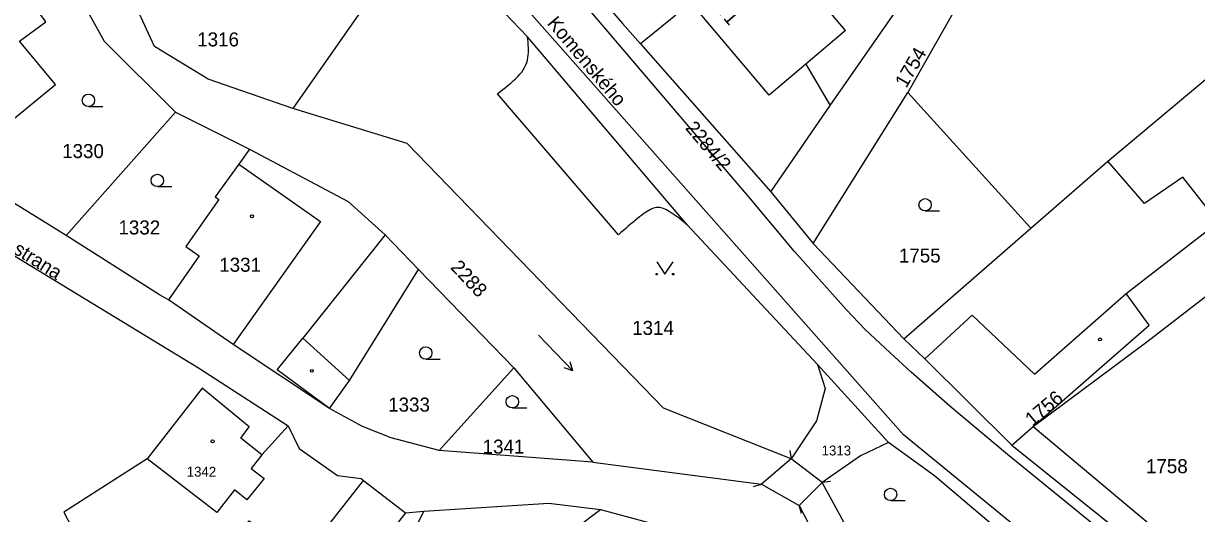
# Model space of a CAD drawing. Extents: x -504988 to -494607, y -1123820 to -1114018.
# Drawn here: x -498003.8 to -497861.7, y -1119159 to -1119099.6 of the extents above; entities that cross this region are included whole.
import ezdxf

# ---------------------------------------------------------------- set-up
doc = ezdxf.new("R2010")
doc.units = 0
for name, color, linetype in [('Hranice parcel', 7, 'Continuous'), ('Parcelní čísla', 7, 'Continuous'), ('Pop  PČ popisy', 7, 'Continuous'), ('Vnitřní kresba', 7, 'Continuous'), ('Značky budov', 7, 'Continuous'), ('Značky kultur', 7, 'Continuous')]:
    doc.layers.add(name, color=color, linetype=linetype)

msp = doc.modelspace()

# ---------------------------------------------------------------- linework, layer by layer
at = {"layer": 'Hranice parcel'}
for p, q in [((-497887.77, -1119092.18), (-497896.72, -1119107.97)), ((-497961.64, -1119096.18), (-497971.21, -1119109.91)), ((-497908.17, -1119126.25), (-497896.72, -1119107.97)), ((-497896.72, -1119107.97), (-497881.83, -1119124.42)), ((-497998.68, -1119125.28), (-497985.41, -1119110.35)), ((-497985.41, -1119110.35), (-497976.46, -1119114.83)), ((-497998.68, -1119125.28), (-498012.13, -1119116.99)), ((-497881.83, -1119124.42), (-497872.49, -1119116.3)), ((-497913.33, -1119120.02), (-497908.17, -1119126.25)), ((-497897.22, -1119137.82), (-497881.83, -1119124.42)), ((-497908.17, -1119126.25), (-497897.22, -1119137.82)), ((-497955.98, -1119129.4), (-497944.43, -1119141.34)), ((-497899.04, -1119150.4), (-497907.66, -1119140.94)), ((-497953.5, -1119151.34), (-497944.43, -1119141.34)), ((-497944.43, -1119141.34), (-497934.86, -1119152.78)), ((-497884.11, -1119150.7), (-497881.53, -1119148.44)), ((-497884.11, -1119150.7), (-497809.18, -1119210.79)), ((-497934.86, -1119152.78), (-497953.5, -1119151.34)), ((-497907.08, -1119155.23), (-497910.85, -1119152.35)), ((-497934.86, -1119152.78), (-497914.46, -1119155.42)), ((-497962.63, -1119154.98), (-497957.58, -1119158.92)), ((-497914.46, -1119155.42), (-497909.86, -1119158.02)), ((-497893.36, -1119180.26), (-497907.08, -1119155.23)), ((-497955.35, -1119158.69), (-497961.68, -1119170.97)), ((-497957.58, -1119158.92), (-497955.35, -1119158.69)), ((-497933.93, -1119158.49), (-497922.1, -1119161.69))]:
    msp.add_line(p, q, dxfattribs=at)
for points in [[(-497910.46, -1119127.22), (-497915.79, -1119120.84), (-497965.51, -1119062.43), (-497969.8, -1119056.29)], [(-497971.21, -1119109.91), (-497981.48, -1119106.35), (-497987.95, -1119102.39), (-497996.54, -1119083.76)], [(-498003.97, -1119085.2), (-498000.56, -1119092.53), (-497998.87, -1119093.04), (-497994.08, -1119101.73), (-497985.41, -1119110.35)], [(-497942.7, -1119086.56), (-497936.66, -1119093.43), (-497933.96, -1119096.51), (-497931.26, -1119099.59), (-497929.09, -1119102.07), (-497913.33, -1119120.02)], [(-497907.66, -1119140.94), (-497923.43, -1119123.99), (-497942.78, -1119101.23), (-497953.93, -1119089.55)], [(-497872.49, -1119116.3), (-497843.78, -1119092.19), (-497840.07, -1119088.75)], [(-498012.13, -1119116.99), (-497999.97, -1119107), (-498004.3, -1119101.73), (-498001.13, -1119099.4), (-498002.9, -1119096.92), (-498003.95, -1119097.55), (-498005.62, -1119095.27), (-498011.54, -1119099.6), (-498020.88, -1119106.56)], [(-497913.33, -1119120.02), (-497906.12, -1119109.53), (-497896.94, -1119096.33)], [(-497910.85, -1119152.35), (-497926.33, -1119146.21), (-497957.34, -1119114.14), (-497971.21, -1119109.91)], [(-497976.46, -1119114.83), (-497977.76, -1119116.63), (-497980.6, -1119120.62), (-497980.18, -1119120.93), (-497984.18, -1119126.62), (-497982.56, -1119127.74), (-497986.27, -1119133.1)], [(-497976.46, -1119114.83), (-497964.52, -1119121.18), (-497960.01, -1119125.23), (-497955.98, -1119129.4)], [(-497881.53, -1119148.44), (-497867.5, -1119136.16), (-497870.27, -1119132.33), (-497859.11, -1119123.69), (-497863.39, -1119118.22), (-497868.05, -1119121.43), (-497872.49, -1119116.3)], [(-497881.53, -1119148.44), (-497867.76, -1119138.19), (-497847.62, -1119122.61)], [(-498010.34, -1119124.5), (-497982.64, -1119141.32), (-497971.78, -1119148.38)], [(-497986.27, -1119133.1), (-497987.35, -1119132.48), (-497998.68, -1119125.28)], [(-497901.88, -1119136.7), (-497904.2, -1119134.26), (-497910.46, -1119127.22)], [(-497966.75, -1119146.25), (-497964.36, -1119142.85), (-497955.98, -1119129.4)], [(-497966.75, -1119146.25), (-497978.45, -1119138.5), (-497986.27, -1119133.1)], [(-497896.33, -1119141.86), (-497898.9, -1119139.46), (-497901.88, -1119136.7)], [(-497897.22, -1119137.82), (-497894.64, -1119140.25), (-497884.11, -1119150.7)], [(-497907.66, -1119140.94), (-497906.71, -1119143.85), (-497907.76, -1119147.75), (-497910.85, -1119152.35)], [(-497884.63, -1119151.84), (-497891.61, -1119145.97), (-497896.33, -1119141.86)], [(-497971.78, -1119148.38), (-497974.95, -1119151.88), (-497977.52, -1119149.84), (-497976.48, -1119148.47), (-497982.2, -1119143.81), (-497988.87, -1119152.35), (-497998.96, -1119158.81), (-497996.1, -1119164.22)], [(-497953.5, -1119151.34), (-497959.31, -1119149.81), (-497962.78, -1119148.46), (-497966.75, -1119146.25)], [(-497971.78, -1119148.38), (-497970.45, -1119151.11), (-497965.81, -1119154.39), (-497962.94, -1119154.75), (-497962.63, -1119154.98)], [(-497881.53, -1119148.44), (-497865.6, -1119161.82), (-497860.83, -1119165.86)], [(-497899.04, -1119150.4), (-497902.43, -1119152.01), (-497907.08, -1119155.23)], [(-497871.82, -1119172.7), (-497879.99, -1119165.84), (-497893.49, -1119154.44), (-497899.04, -1119150.4)], [(-497812.29, -1119211.08), (-497844.48, -1119184.57), (-497884.63, -1119151.84)], [(-497957.58, -1119158.92), (-497968.08, -1119172.34), (-497979.3, -1119163.51), (-497976.5, -1119159.89), (-497970.28, -1119164.73), (-497962.63, -1119154.98)], [(-497955.35, -1119158.69), (-497940.22, -1119157.75), (-497933.93, -1119158.49)], [(-497909.86, -1119158.02), (-497892.71, -1119191.12), (-497876.63, -1119210.93), (-497865.83, -1119233.14)], [(-497948.45, -1119177.35), (-497942.81, -1119172.64), (-497946.55, -1119168.01), (-497933.93, -1119158.49)]]:
    msp.add_lwpolyline(points, dxfattribs=at)
at = {"layer": 'Vnitřní kresba'}
for p, q in [((-497897.25, -1119149.44), (-497970.37, -1119066.76)), ((-497904.25, -1119100.45), (-497909.96, -1119093.72)), ((-497913.51, -1119108.29), (-497922.99, -1119097.04)), ((-497924.83, -1119098.59), (-497929.09, -1119102.07)), ((-497904.25, -1119100.45), (-497909.07, -1119104.53)), ((-497909.07, -1119104.53), (-497913.51, -1119108.29)), ((-497909.07, -1119104.53), (-497906.12, -1119109.53)), ((-497931.76, -1119125.21), (-497946.43, -1119108.11)), ((-497977.76, -1119116.63), (-497967.85, -1119123.58)), ((-497967.85, -1119123.58), (-497978.45, -1119138.5)), ((-497960.01, -1119125.23), (-497970, -1119137.75)), ((-497881.39, -1119142.11), (-497870.27, -1119132.33)), ((-497894.64, -1119140.25), (-497888.94, -1119134.95)), ((-497888.94, -1119134.95), (-497881.39, -1119142.11)), ((-497973.1, -1119141.57), (-497970, -1119137.75)), ((-497970, -1119137.75), (-497964.36, -1119142.85)), ((-497966.75, -1119146.25), (-497973.1, -1119141.57)), ((-497872.02, -1119170.07), (-497897.25, -1119149.44)), ((-497980.41, -1119158.88), (-497988.87, -1119152.35)), ((-497974.95, -1119151.88), (-497976.24, -1119153.55)), ((-497910.85, -1119152.35), (-497914.46, -1119155.42)), ((-497910.99, -1119151.36), (-497910.85, -1119152.35)), ((-497976.24, -1119153.55), (-497974.7, -1119154.73)), ((-497974.7, -1119154.73), (-497976.76, -1119157.31)), ((-497915.42, -1119155.7), (-497914.46, -1119155.42)), ((-497909.86, -1119158.02), (-497907.08, -1119155.23)), ((-497906.09, -1119155.09), (-497907.08, -1119155.23)), ((-497978.26, -1119156.11), (-497980.41, -1119158.88)), ((-497976.76, -1119157.31), (-497978.26, -1119156.11)), ((-497909.59, -1119158.98), (-497909.86, -1119158.02))]:
    msp.add_line(p, q, dxfattribs=at)
for points in [[(-497946.43, -1119108.11), (-497946.1, -1119107.86), (-497945.76, -1119107.6), (-497945.43, -1119107.34), (-497945.11, -1119107.08), (-497944.8, -1119106.82), (-497944.5, -1119106.56), (-497944.22, -1119106.3), (-497943.96, -1119106.03), (-497943.71, -1119105.76), (-497943.49, -1119105.49), (-497943.3, -1119105.2), (-497943.13, -1119104.92), (-497942.99, -1119104.63), (-497942.88, -1119104.34), (-497942.8, -1119104.04), (-497942.74, -1119103.74), (-497942.7, -1119103.43), (-497942.68, -1119103.12), (-497942.67, -1119102.81), (-497942.68, -1119102.5), (-497942.7, -1119102.18), (-497942.72, -1119101.87), (-497942.75, -1119101.55), (-497942.78, -1119101.23)], [(-497923.43, -1119123.99), (-497923.68, -1119123.79), (-497923.93, -1119123.59), (-497924.18, -1119123.4), (-497924.43, -1119123.21), (-497924.67, -1119123.02), (-497924.91, -1119122.85), (-497925.15, -1119122.69), (-497925.38, -1119122.53), (-497925.61, -1119122.39), (-497925.82, -1119122.27), (-497926.04, -1119122.16), (-497926.24, -1119122.07), (-497926.43, -1119122), (-497926.62, -1119121.95), (-497926.81, -1119121.92), (-497926.98, -1119121.91), (-497927.17, -1119121.92), (-497927.34, -1119121.95), (-497927.52, -1119122), (-497927.71, -1119122.06), (-497927.89, -1119122.15), (-497928.09, -1119122.25), (-497928.29, -1119122.38), (-497928.51, -1119122.52), (-497928.74, -1119122.68), (-497928.98, -1119122.86), (-497929.23, -1119123.05), (-497929.48, -1119123.25), (-497929.75, -1119123.47), (-497930.02, -1119123.7), (-497930.3, -1119123.94), (-497930.59, -1119124.18), (-497930.88, -1119124.44), (-497931.17, -1119124.69), (-497931.47, -1119124.95), (-497931.76, -1119125.21)]]:
    msp.add_lwpolyline(points, dxfattribs=at)
at = {"layer": 'Značky budov'}
for centre in [(-497976.16, -1119122.97), (-497873.44, -1119137.89), (-497968.91, -1119141.69), (-497980.92, -1119150.24)]:
    msp.add_circle(centre, 0.175, dxfattribs=at)
at = {"layer": 'Značky kultur'}
for p, q in [((-497995.97, -1119109.66), (-497994.22, -1119109.66)), ((-497987.62, -1119119.37), (-497985.87, -1119119.37)), ((-497894.62, -1119122.32), (-497892.87, -1119122.32)), ((-497941.47, -1119137.36), (-497937.3, -1119141.68)), ((-497955.11, -1119140.28), (-497953.36, -1119140.28)), ((-497937.3, -1119141.68), (-497937.62, -1119140.62)), ((-497937.3, -1119141.68), (-497938.34, -1119141.32)), ((-497944.62, -1119146.19), (-497942.87, -1119146.19)), ((-497898.8, -1119157.42), (-497897.05, -1119157.42))]:
    msp.add_line(p, q, dxfattribs=at)
msp.add_lwpolyline([(-497927.13, -1119128.48), (-497926.13, -1119129.98), (-497925.13, -1119128.48)], dxfattribs=at)
for centre, radius in [((-497995.97, -1119108.91), 0.75), ((-497987.62, -1119118.62), 0.75), ((-497894.62, -1119121.57), 0.75), ((-497927.13, -1119129.98), 0.1), ((-497925.13, -1119129.98), 0.1), ((-497955.11, -1119139.53), 0.75), ((-497944.62, -1119145.44), 0.75), ((-497898.8, -1119156.67), 0.75)]:
    msp.add_circle(centre, radius, dxfattribs=at)

# ---------------------------------------------------------------- texts
at = {"layer": 'Parcelní čísla'}
for s, rotation, p in [('1753/1', 311, (-497922.88, -1119094.69)), ('1754', 60, (-497896.91, -1119107.52)), ('2284/2', 310, (-497923.75, -1119112.31)), ('2288', 313, (-497952.2, -1119129.23)), ('1756', 40, (-497881.63, -1119148.5))]:
    msp.add_text(s, height=1.7, rotation=rotation, dxfattribs=at).set_placement(p)
for s, height, p in [('1316', 1.7, (-497982.79, -1119102.38)), ('1330', 1.7, (-497999.15, -1119115.91)), ('1332', 1.7, (-497992.33, -1119125.17)), ('1755', 1.7, (-497897.8, -1119128.57)), ('1331', 1.7, (-497980.12, -1119129.69)), ('1314', 1.7, (-497930.11, -1119137.34)), ('1333', 1.7, (-497959.66, -1119146.64)), ('1341', 1.7, (-497948.22, -1119151.73)), ('1313', 1.2, (-497907.16, -1119151.95)), ('1758', 1.7, (-497867.87, -1119154.1)), ('1342', 1.2, (-497984.06, -1119154.52))]:
    msp.add_text(s, height=height, dxfattribs=at).set_placement(p)
at = {"layer": 'Pop  PČ popisy'}
for s, rotation, p in [('Komenského', 310, (-497940.49, -1119099.62)), ('Malá strana', 328, (-498009.92, -1119124.42))]:
    msp.add_text(s, height=1.7, rotation=rotation, dxfattribs=at).set_placement(p)

doc.saveas('drawing.dxf')
